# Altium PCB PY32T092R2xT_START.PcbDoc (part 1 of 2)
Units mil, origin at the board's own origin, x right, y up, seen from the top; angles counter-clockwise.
Board outline 1771.65 x 3866.06 mil, 2 copper layers (Top Layer, Bottom Layer), stack 21 mil thick; 144 components, 162 nets, 571 pads, 266 vias.
Unrouted connection lines stored in the file: 5.
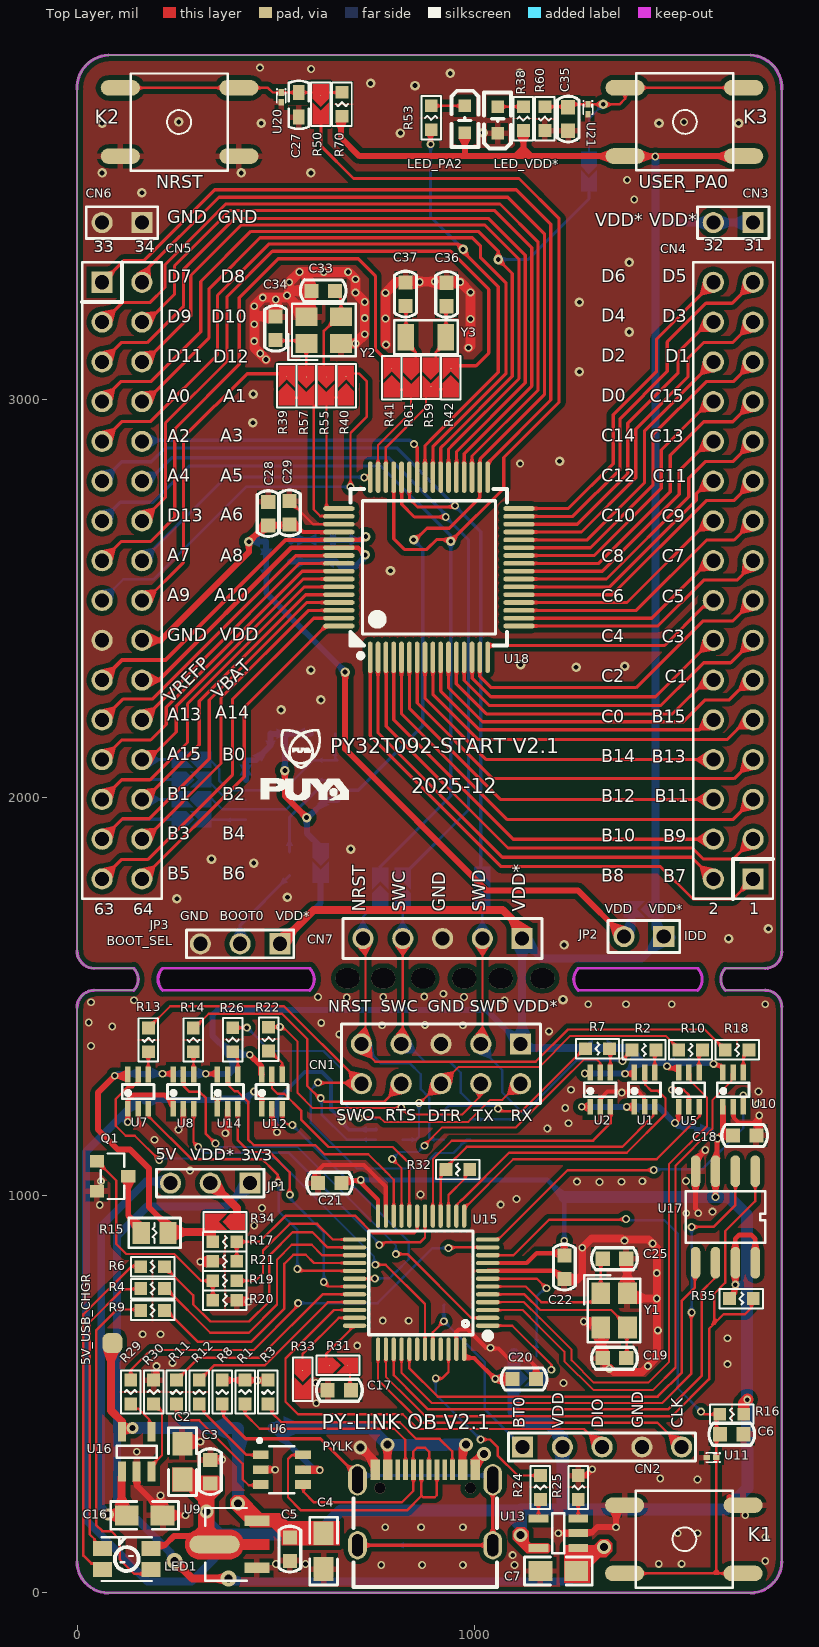
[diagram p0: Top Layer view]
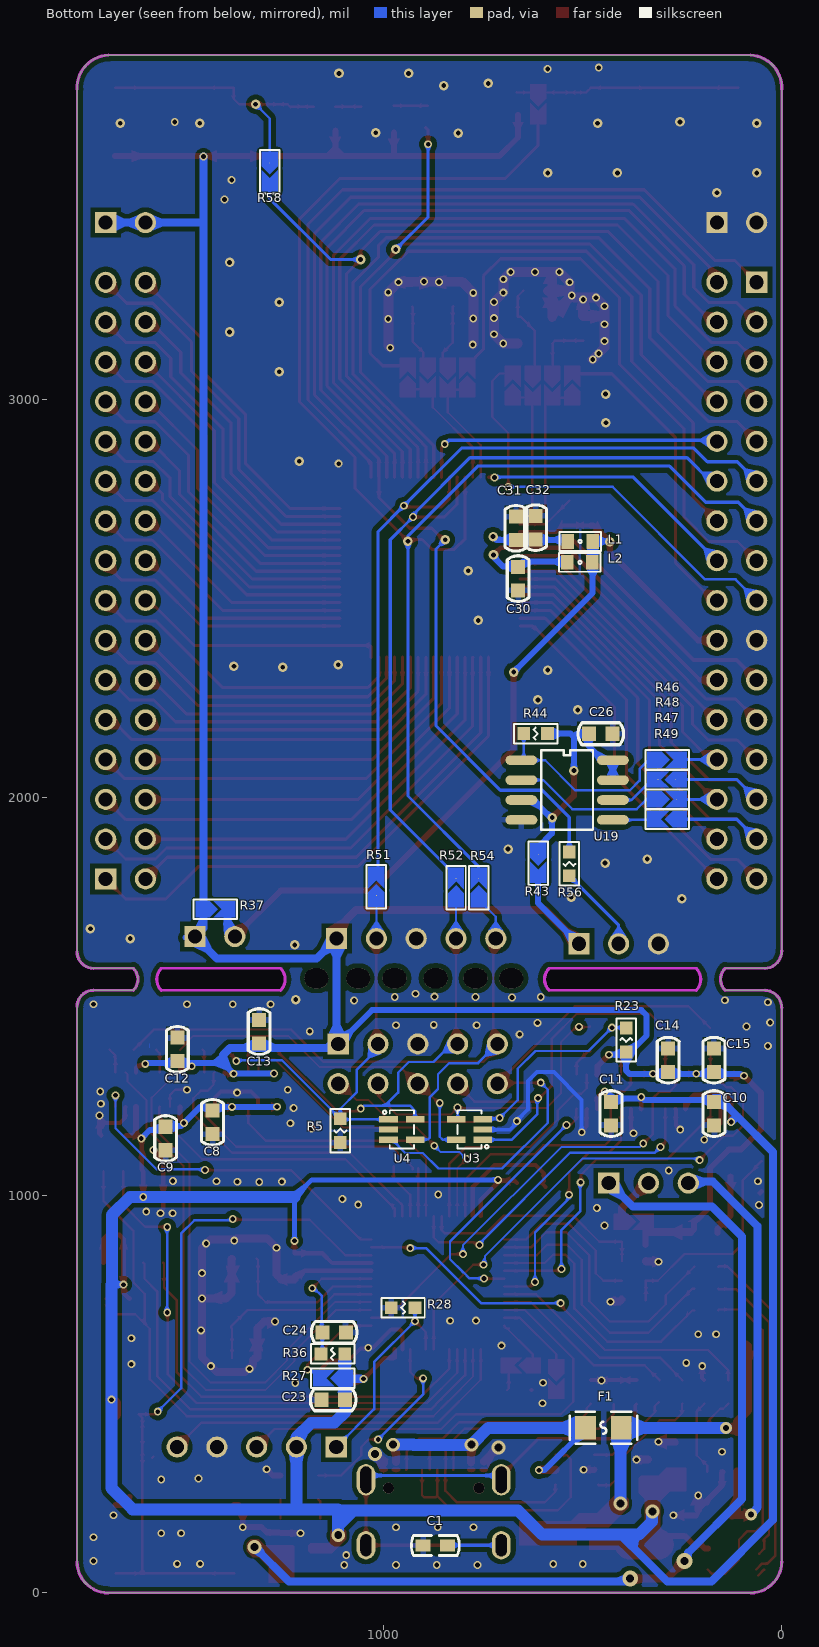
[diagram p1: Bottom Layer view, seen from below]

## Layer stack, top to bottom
Top Solder: solder mask 0.4, Solder Resist, Dk 3.5
Top Layer: signal copper 1.4
Dielectric 2: prepreg 2.8, Composite dielectric, Dk 4.1
Dielectric 1: prepreg 12.6, Composite dielectric, Dk 4.1
Dielectric 3: prepreg 2.8, Composite dielectric, Dk 4.1
Bottom Layer: signal copper 1.4
Bottom Solder: solder mask 0.4, Solder Resist, Dk 3.5

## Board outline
0.02,78.86 0.02,1470.12 cw(c43.77,1471.37) 42.52,1515.12 142.52,1515.12 ccw(c115.02,1542.62) 142.52,1570.12 42.52,1570.12 cw(c43.77,1613.87) 0.02,1615.12 0.02,3779.64 cw(c82.65,3783.54) 78.76,3866.18 1692.93,3866.18 cw(c1689.03,3783.54) 1771.67,3779.64 1771.67,1611.77 cw(c1730.02,1611.77) 1730.02,1570.12 1630.02,1570.12 ccw(c1657.52,1542.62) 1630.02,1515.12 1730.02,1515.12 cw(c1730.02,1473.46) 1771.67,1473.46 1771.67,78.86 cw(c1692.93,78.86) 1692.93,0.12 78.76,0.12 cw(c78.76,78.86)
cut-out: 215.02,1515.12 cw(c242.52,1542.62) 215.02,1570.12 585.02,1570.12 cw(c557.52,1542.62) 585.02,1515.12 565.02,1515.12
cut-out: 1260.02,1515.12 cw(c1287.52,1542.62) 1260.02,1570.12 1560.02,1570.12 cw(c1532.52,1542.62) 1560.02,1515.12

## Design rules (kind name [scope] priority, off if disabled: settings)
Clearance polygon [InPolygon] p1: gap=12 ignorepadtopadclearanceinfootprint=TRUE
Clearance [All] p2: gap=7 ignorepadtopadclearanceinfootprint=TRUE
HoleToHoleClearance [All] p1: gap=1 allowstackedmicrovias=TRUE
MinimumSolderMaskSliver [All] p1: minsoldermaskwidth=0
PlaneClearance [All] p1: clearance=8
PlaneConnect [All] p1: planeconnectstyle=Direct reliefexpansion=20 reliefentries=4 reliefconductorwidth=10 reliefairgap=10
PolygonConnect [All] p1: thpad.connectstyle=Direct thpad.reliefconductorwidth=10 thpad.reliefentries=4 thpad.polygonreliefangle="90 Angle" thpad.airgapwidth=10 smdpad.connectstyle=Relief smdpad.reliefconductorwidth=15 smdpad.reliefentries=4 smdpad.polygonreliefangle="90 Angle" smdpad.airgapwidth=10 via.connectstyle=Direct via.reliefconductorwidth=10 via.reliefentries=4 via.polygonreliefangle="90 Angle" via.airgapwidth=10
RoutingVias [All] p1: holewidth=28 width=50 viastyle="Through Hole" minholewidth=28 minwidth=50 maxholewidth=28 maxwidth=50
SilkToSilkClearance [All] p1: silktosilkclearance=0
SilkToSolderMaskClearance [IsPad] p1: minsilkscreentomaskgap=0 clearancetoexposedcopper=TRUE
SolderMaskExpansion [All] p1: expansion=4 istentingtop=FALSE
UnRoutedNet [All] p1: checkbadconnections=TRUE
Width [All] p1: maxlimit=100 minlimit=5 preferedwidth=8
23 further rules are at their usual default settings.

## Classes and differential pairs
component class PY32F092R2xT_START: 3 C26 C27 C28 C29 C30 C31 C32 C33 C34 C35 C36 C37 CN3 CN4 CN5 CN6 CN7 JP2 JP3 K2 K3 L1 L2 LED_PA2 LED_VDD* R37 R38 R39 R40 R41 R42 R43 R44 R46 R47 R48 R49 R50 R51 R52 R53 R54 R55 R56 R57 R58 R59 R60 R61 R70 U18 U19 U20 U21 Y2 Y3
component class PY32F403C1xT_LINK: 5V_USB_CHGR C1 C2 C3 C4 C5 C6 C7 C8 C9 C10 C11 C12 C13 C14 C15 C16 C17 C18 C19 C20 C21 C22 C23 C24 C25 CN1 CN2 F1 JP1 K1 LED1 PYLK Q1 R1 R2 R3 R4 R5 R6 R7 R8 R9 R10 R11 R12 R13 R14 R15 R16 R17 R18 R19 R20 R21 R22 R23 R24 R25 R26 R27 R28 R29 R30 R31 R32 R33 R34 R35 R36 U1 U2 U3 U4 U5 U6 U7 U8 U9 U10 U11 U12 U13 U14 U15 U16 U17 Y1

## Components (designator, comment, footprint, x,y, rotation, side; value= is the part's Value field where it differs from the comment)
5V_USB_CHGR "TP_SIN" TP_SIN 89.03,628.05 r90 top
C1 "4.7nF" C0603#1 870.87,119.29 r180 bottom
C2 "10uF" C0805 265.02,330.12 r270 top
C3 "100nF" C0603#2 335.02,305.12 r270 top
C4 "10uF" C0805 620.02,105.12 r90 top
C5 "100nF" C0603#2 535.02,110.12 r90 top
C6 "100nF" C0603#2 1646.06,398.88 r180 top
C7 "10uF" C0805 1210.02,55.12 r0 top
C8 "100nF" C0603#2 1431.02,1183.12 r90 bottom value=104
C9 "100nF" C0603#2 1548.92,1142.42 r90 bottom value=104
C10 "100nF" C0603#2 170.22,1205.02 r90 bottom value=104
C11 "100nF" C0603#2 429.02,1205.02 r90 bottom value=104
C12 "100nF" C0603#2 1519.42,1366.72 r270 bottom value=104
C13 "100nF" C0603#2 1313.82,1411.22 r270 bottom value=104
C14 "100nF" C0603#2 285.52,1339.32 r270 bottom value=104
C15 "100nF" C0603#2 170.52,1339.32 r270 bottom value=104
C16 "10uF" C0805 170.02,195.12 r180 top
C17 "100nF" C0603#2 659.61,509.61 r0 top
C18 "100nF" C0603#2 1678.35,1150 r180 top value=104
C19 "22pF" C0603#2 1351.14,590.12 r0 top
C20 "100nF" C0603#2 1123.88,537.71 r180 top value=104
C21 "100nF" C0603#2 635.02,1030.12 r0 top value=104
C22 "100nF" C0603#2 1225.14,819.12 r90 top value=104
C23 "100nF" C0603#2 1127.75,485.69 r180 bottom value=104
C24 "100nF" C0603#2 1125.14,655.12 r0 bottom value=104
C25 "22pF" C0603#2 1351.14,840.12 r180 top
C26 "100nF" C0603#2 454.91,2159.85 r0 bottom value=104
C27 "100nF" C0603#1 557.48,3740.94 r90 top
C28 "4.7uF" C0603#2 480.82,2713.43 r90 top
C29 "100nF" C0603#2 533.81,2715.26 r90 top
C30 "1uF" C0603#2 662.65,2549.82 r270 bottom
C31 "1uF" C0603#2 668.16,2676.43 r90 bottom
C32 "100nF" C0603#2 618.82,2677.94 r90 bottom
C33 "22pF" C0603#2 618.83,3273.44 r0 top
C34 "22pF" C0603#2 499.4,3179.12 r270 top
C35 "100nF" C0603#2 1234.75,3705.26 r90 top
C36 "22pF" C0603#2 929.21,3264.24 r270 top
C37 "22pF" C0603#2 826.04,3265.25 r270 top
CN1 "2X5P" HDR2X5 1115.02,1380.12 r180 top
CN2 "CON5" CON5 1120.06,366.88 r0 top
CN3 "CON2" CON2 1699.61,3444.88 r180 top
CN4 "2X16P 2.54mm" HDR-TH_32P-P2.54-V-M-R2-C16-S2.54-3 1649.61,2544.88 r90 top locked
CN5 "2X16P 2.54mm" HDR-TH_32P-P2.54-V-M-R2-C16-S2.54-3 113.06,2544.88 r270 top locked
CN6 "CON2" CON2 163.06,3444.88 r180 top
CN7 "Header 5" HDR1X5 1118.95,1645.12 r180 top
F1 "JK-SMD0805-050-16V" F0805 448.43,415.35 r180 bottom
JP1 "CON3" CON3 435.02,1030.12 r180 top
JP2 "CON2/NC" CON2 1475.02,1650.12 r180 top
JP3 "CON3" CON3 510.06,1631.88 r180 top
K1 "TS-KG02S-AT43F" SW-SMD_4P-L6.0-W6.0-P4.50-LS8.5 1527.56,134.82 r180 top
K2 "TS-KG02S-AT43F" SW-SMD_4P-L6.0-W6.0-P4.50-LS8.5 255.8,3697.92 r0 top
K3 "TS-KG02S-AT43F" SW-SMD_4P-L6.0-W6.0-P4.50-LS8.5 1528.95,3697.9 r180 top
L1 "BEAD" L0603 507,2643.32 r0 bottom value=600R@100MHz
L2 "BEAD" L0603 507.48,2590.94 r0 bottom value=600R@100MHz
LED1 "MHPA3528RGBCT" LED-ARRAY-SMD_4P-L3.5-W2.8-TL 125.02,85.12 r0 top
LED_PA2 "GREEN" 0603_LED 974.21,3690.35 r270 top
LED_VDD* "RED" 0603_LED 1058.21,3717.35 r90 top
PYLK "KH-TYPE-C-16P" USB-C-SMD_KH-TYPE-C-16P 875.22,214.93 r0 top locked
Q1 "2302" SOT23 89.39,1047.52 r90 top value=SI2302
R1 "5.1K" R0603 422.51,505.11 r270 top
R2 "27R" R0603 1425.22,1365.12 r180 top
R3 "5.1K" R0603 480.02,505.12 r90 top
R4 "680R" R0603 190.02,765.12 r0 top
R5 "1M" R0603 1109.84,1162.2 r90 bottom
R6 "680R" R0603 190.02,820.12 r0 top
R7 "27R" R0603 1308.41,1368.22 r180 top
R8 "1M" R0603 365.02,505.12 r90 top
R9 "680R" R0603 190.02,710.12 r0 top
R10 "27R" R0603 1542.37,1365.12 r180 top
R11 "27R" R0603 250.02,505.12 r90 top
R12 "27R" R0603 307.52,505.12 r90 top
R13 "27R" R0603 179.67,1390.2 r90 top
R14 "27R" R0603 292.32,1390.22 r90 top
R15 "100R" R0805 195.02,905.12 r0 top
R16 "10K" R0603 1646.06,448.88 r0 top
R17 "20K" R0603 371.53,882.72 r180 top
R18 "27R" R0603 1659.51,1365.12 r180 top
R19 "100R" R0603 371.54,784.9 r0 top
R20 "100K" R0603 371.53,736 r180 top
R21 "10K" R0603 371.54,833.8 r0 top
R22 "27R" R0603 481.65,1392.23 r90 top
R23 "4.7K" R0603 391.02,1390.12 r270 bottom
R24 "4.7K" R0603 1165.02,265.12 r270 top
R25 "16K" R0603 1260.24,264.96 r270 top
R26 "27R" R0603 391.22,1390.82 r90 top
R27 "0R" JP2_SMD 1128.36,539.95 r180 bottom
R28 "10K" R0603 952.02,717.19 r0 bottom
R29 "4.7K" R0603 135.02,505.12 r270 top
R30 "16K" R0603 192.52,505.12 r270 top
R31 "0R" JP2_SMD 656.23,571.86 r180 top
R32 "680R" R0603 957.48,1064.48 r0 top
R33 "0R" JP2_SMD 566.98,537.51 r90 top
R34 "0R" JP2_SMD 372.06,932.88 r0 top
R35 "100K" R0603 1670.02,740.12 r180 top
R36 "10K" R0603 1128.61,600.73 r180 bottom
R37 "0R" JP2_SMD 1423.77,1718.47 r0 bottom
R38 "680R" R0603 1122.21,3706.35 r270 top
R39 "0R" JP2_SMD 527.02,3035.12 r270 top
R40 "0R" JP2_SMD 676.23,3035.12 r270 top
R41 "0R" JP2_SMD 791.02,3055.12 r270 top
R42 "0R" JP2_SMD 940.02,3055.12 r270 top
R43 "0R/NC" JP2_SMD 612.32,1834.56 r90 bottom
R44 "100K" R0603 618.75,2160.34 r180 bottom
R46 "0R/NC" JP2_SMD 288.06,2094.88 r0 bottom
R47 "0R/NC" JP2_SMD 288.06,1994.88 r0 bottom
R48 "0R/NC" JP2_SMD 288.06,2044.88 r180 bottom
R49 "0R/NC" JP2_SMD 288.06,1944.88 r180 bottom
R50 "0R" JP2_SMD 612.6,3742.52 r90 top
R51 "100R" JP2_SMD 1018.95,1775.18 r270 bottom
R52 "100R" JP2_SMD 818.95,1773.12 r270 bottom
R53 "680R" R0603 890.21,3708.35 r270 top
R54 "0R" JP2_SMD 762.02,1773.12 r270 bottom
R55 "0R" JP2_SMD 626.5,3035.13 r90 top
R56 "10K" R0603 534.06,1832.88 r90 bottom
R57 "0R" JP2_SMD 576.76,3035.13 r90 top
R58 "0R" JP2_SMD 1287.02,3573.12 r90 bottom
R59 "0R" JP2_SMD 889.68,3055.94 r90 top
R60 "1.5K" R0603 1176.21,3706.35 r90 top
R61 "0R" JP2_SMD 840,3055.43 r90 top
R70 "10K" R0603 666.14,3742.52 r90 top
U1 "74LVC1T45DW" SOT363 1426.65,1265.12 r0 top
U2 "74LVC1T45DW" SOT363 1315.22,1265.12 r0 top
U3 "ESDALC6V1W5" ESD_SOT323-5L 785.02,1165.12 r90 bottom
U4 "ESDALC6V1W5" ESD_SOT323-5L 955.02,1165.12 r270 bottom
U5 "74LVC1T45DW" SOT363 1538.08,1265.12 r0 top locked
U6 "USBLC6-2SC6" SOT23-6 515.02,310.12 r90 top
U7 "74LVC1T45DW" SOT363 153.56,1260.12 r0 top locked
U8 "74LVC1T45DW" SOT363 267.28,1260.12 r0 top
U9 "LM1117F-3.3" SOT-89-3_L4.5-W2.5-P1.50-LS4.2-BR 399.06,122.05 r0 top
U10 "74LVC1T45DW" SOT363 1649.51,1265.12 r0 top
U11 "ESDALC6V1-1U2" ESD_ST0201 1595.02,340.12 r180 top
U12 "74LVC1T45DW" SOT363 490.14,1260.12 r0 top
U13 "MT9700" SOT23-5 1210.02,150.12 r90 top
U14 "74LVC1T45DW" SOT363 378.71,1260.12 r0 top
U15 "PY32F403C1xT" LQFP-48_L7.0-W7.0-P0.50-LS9.0-BL 865.02,780.12 r90 top locked
U16 "MT9700" SOT23-5 150.02,355.12 r0 top
U17 "P25Q64SH" SOP-8P 1630.02,945.12 r180 top value=SST25VF020B
U18 "PY32F092R2xT" LQFP-64_L10.0-W10.0-P0.50-LS12.0-BL 884.67,2578.43 r0 top locked
U19 "P25Q64SH" SOP-8P 539.58,2018.32 r270 bottom value=SST25VF020B
U20 "ESDALC6V1-1U2" ESD_ST0201 513.51,3759.59 r270 top
U21 "ESDALC6V1-1U2" ESD_ST0201 1284.25,3729.92 r270 top
Y1 "24MHz" CRYSTAL-SMD_4P-L3.2-W2.5-BL 1350.14,710.12 r270 top
Y2 "24MHz" CRYSTAL-SMD_4P-L3.2-W2.5-BL 620.36,3174.54 r0 top
Y3 "32.768KHz" CRYSTAL-SMD_L3.2-W1.5-1 877.12,3156.52 r0 top value=32.768kHz

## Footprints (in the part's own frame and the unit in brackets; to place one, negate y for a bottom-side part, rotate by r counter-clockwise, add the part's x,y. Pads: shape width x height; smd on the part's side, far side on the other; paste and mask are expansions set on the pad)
0603_LED [mil]
  rect 31.5x31.5 smd: 1(19,1) 2(-48,1)
  silkscreen extent -86,-33 55,35
C0603#1 [mil]
  rect 38x30 smd: 1(-31,0) 2(31,0)
  silkscreen extent -60,-25 60,25
C0603#2 [mil]
  rect 35.43x35.43 smd: 1(-29.53,0) 2(29.53,0)
  silkscreen extent -57,-28 57,28
C0805 [mil]
  rect 60x50 smd: 1(-45,0) 2(45,0)
  silkscreen extent -85,-35 85,35
CON2 [mm]
  rect 1.35x1.35 hole 0.9: 1(0,0)
  round 1.35 hole 0.9: 2(2.54,0)
  silkscreen extent -1.02,-1.02 3.56,1.02
CON3 [mm]
  rect 1.35x1.35 hole 0.9: 1(0,0)
  round 1.35 hole 0.9: 2(2.54,0) 3(5.08,0)
  silkscreen extent -0.89,-0.89 5.97,0.89
CON5 [mm]
  rect 1.35x1.35 hole 0.9: 1(0,0)
  round 1.35 hole 0.9: 2(2.54,0) 3(5.08,0) 4(7.62,0) 5(10.16,0)
  silkscreen extent -0.89,-0.89 11.05,0.89
CRYSTAL-SMD_4P-L3.2-W2.5-BL [mm]
  rect 1.4x1.2 smd: 1(-1.1,-0.85) 2(1.1,-0.85) 3(1.1,0.85) 4(-1.1,0.85)
  silkscreen extent -2.26,-1.91 2.03,1.68
CRYSTAL-SMD_L3.2-W1.5-1 [mm]
  rect 1.05x1.7 smd: 1(-1.275,0) 2(1.275,0)
  silkscreen extent -2.03,-1.08 2.03,1.08
ESD_SOT323-5L [mm]
  rect 0.4x1.2 smd mask+0.05: 1(-0.65,-0.85) 2(0,-0.85) 3(0.65,-0.85) 4(0.65,0.85) 5(-0.65,0.85)
  silkscreen extent -1.23,-1.21 1.23,0.77, body extent -1.15,-1.05 1.15,1.05, height 1.1
ESD_ST0201 [mm]
  rect 0.425x0.33 smd mask+0.05: 1(-0.312,0) 2(0.312,0)
  silkscreen extent -0.55,-0.3 0.33,0.3, body extent -0.34,-0.18 0.34,0.18, height 0.34
F0805 [mm]
  rect 1.335x1.5 smd paste-100 mask+0.051: 1(-1.142,0) 2(1.142,0)
  silkscreen extent -2.16,-1.02 2.16,1.02
HDR1X5 [mm] "Connector; Header; 5 Position"
  rect 1.35x1.35 hole 0.9: 1(0,0)
  round 1.35 hole 0.9: 2(2.54,0) 3(5.08,0) 4(7.62,0) 5(10.16,0)
  silkscreen extent -1.27,-1.27 11.43,1.27
HDR2X5 [mm] "Connector; Header; 4x2 Position"
  rect 1.35x1.35 hole 0.9: 1(0,0)
  round 1.35 hole 0.9: 2(0,2.54) 3(2.54,0) 4(2.54,2.54) 5(5.08,0) 6(5.08,2.54) 7(7.62,0) 8(7.62,2.54) 9(10.16,0) 10(10.16,2.54)
  silkscreen extent -1.27,-1.27 11.43,3.81
HDR-TH_32P-P2.54-V-M-R2-C16-S2.54-3 [mm]
  rect 1.35x1.35 hole 0.9: 1(-19.05,-1.27)
  round 1.35 hole 0.9: 2(-19.05,1.27) 3(-16.51,-1.27) 4(-16.51,1.27) 5(-13.97,-1.27) 6(-13.97,1.27) 7(-11.43,-1.27) 8(-11.43,1.27) 9(-8.89,-1.27) 10(-8.89,1.27) 11(-6.35,-1.27) 12(-6.35,1.27) 13(-3.81,-1.27) 14(-3.81,1.27) 15(-1.27,-1.27) 16(-1.27,1.27) 17(1.27,-1.27) 18(1.27,1.27) 19(3.81,-1.27) 20(3.81,1.27) 21(6.35,-1.27) 22(6.35,1.27) 23(8.89,-1.27) 24(8.89,1.27) 25(11.43,-1.27) 26(11.43,1.27) 27(13.97,-1.27) 28(13.97,1.27) 29(16.51,-1.27) 30(16.51,1.27) 31(19.05,-1.27) 32(19.05,1.27)
  silkscreen extent -20.32,-2.54 20.32,2.54
JP2_SMD [mil]
  round 1 smd: 1(21.75,0) 2(-23.03,0.03)
  Top Layer region: -49.77,20.03 -49.77,20.03 3.72,20.03 -16.28,0.03 3.72,-19.98 -49.78,-19.98 -49.78,-19.98
  Top Layer region: -6.25,0 13.75,20 49.75,20 49.75,-20 49.75,-20 13.75,-20
  silkscreen extent -55,-25 54,25
L0603 [mm]
  rect 0.8x0.95 smd mask+0.05: 1(-0.8,0) 2(0.8,0)
  silkscreen extent -1.33,-0.6 1.33,0.6, body extent -0.87,-0.47 0.87,0.47, height 0.95
LED-ARRAY-SMD_4P-L3.5-W2.8-TL [mm]
  rect 1.2x0.95 smd: 1(1.55,0.665) 2(1.55,-0.665) 3(-1.55,-0.665) 4(-1.55,0.665)
  silkscreen extent -1.6,-1.4 1.6,1.4
LQFP-48_L7.0-W7.0-P0.50-LS9.0-BL [mm]
  oval 0.27x1.5 smd mask+0.05: 1(-2.75,-4.25) 2(-2.25,-4.25) 3(-1.75,-4.25) 4(-1.25,-4.25) 5(-0.75,-4.25) 6(-0.25,-4.25) 7(0.25,-4.25) 8(0.75,-4.25) 9(1.25,-4.25) 10(1.75,-4.25) 11(2.25,-4.25) 12(2.75,-4.25) 25(2.75,4.25) 26(2.25,4.25) 27(1.75,4.25) 28(1.25,4.25) 29(0.75,4.25) 30(0.25,4.25) 31(-0.25,4.25) 32(-0.75,4.25) 33(-1.25,4.25) 34(-1.75,4.25) 35(-2.25,4.25) 36(-2.75,4.25)
  oval 1.5x0.27 smd mask+0.05: 13(4.25,-2.75) 14(4.25,-2.25) 15(4.25,-1.75) 16(4.25,-1.25) 17(4.25,-0.75) 18(4.25,-0.25) 19(4.25,0.25) 20(4.25,0.75) 21(4.25,1.25) 22(4.25,1.75) 23(4.25,2.25) 24(4.25,2.75) 37(-4.25,2.75) 38(-4.25,2.25) 39(-4.25,1.75) 40(-4.25,1.25) 41(-4.25,0.75) 42(-4.25,0.25) 43(-4.25,-0.25) 44(-4.25,-0.75) 45(-4.25,-1.25) 46(-4.25,-1.75) 47(-4.25,-2.25) 48(-4.25,-2.75)
  silkscreen extent -3.59,-4.46 3.3,3.34
LQFP-64_L10.0-W10.0-P0.50-LS12.0-BL [mm]
  oval 0.3x2 smd: 1(-3.75,-5.75) 2(-3.25,-5.75) 3(-2.75,-5.75) 4(-2.25,-5.75) 5(-1.75,-5.75) 6(-1.25,-5.75) 7(-0.75,-5.75) 8(-0.25,-5.75) 9(0.25,-5.75) 10(0.75,-5.75) 11(1.25,-5.75) 12(1.75,-5.75) 13(2.25,-5.75) 14(2.75,-5.75) 15(3.25,-5.75) 16(3.75,-5.75) 33(3.75,5.75) 34(3.25,5.75) 35(2.75,5.75) 36(2.25,5.75) 37(1.75,5.75) 38(1.25,5.75) 39(0.75,5.75) 40(0.25,5.75) 41(-0.25,5.75) 42(-0.75,5.75) 43(-1.25,5.75) 44(-1.75,5.75) 45(-2.25,5.75) 46(-2.75,5.75) 47(-3.25,5.75) 48(-3.75,5.75)
  oval 2x0.3 smd: 17(5.75,-3.75) 18(5.75,-3.25) 19(5.75,-2.75) 20(5.75,-2.25) 21(5.75,-1.75) 22(5.75,-1.25) 23(5.75,-0.75) 24(5.75,-0.25) 25(5.75,0.25) 26(5.75,0.75) 27(5.75,1.25) 28(5.75,1.75) 29(5.75,2.25) 30(5.75,2.75) 31(5.75,3.25) 32(5.75,3.75) 49(-5.75,3.75) 50(-5.75,3.25) 51(-5.75,2.75) 52(-5.75,2.25) 53(-5.75,1.75) 54(-5.75,1.25) 55(-5.75,0.75) 56(-5.75,0.25) 57(-5.75,-0.25) 58(-5.75,-0.75) 59(-5.75,-1.25) 60(-5.75,-1.75) 61(-5.75,-2.25) 62(-5.75,-2.75) 63(-5.75,-3.25) 64(-5.75,-3.75)
  silkscreen extent -5,-5.79 5,5
R0603 [mil]
  rect 32x32 smd: 1(-30,0) 2(30,0)
  silkscreen extent -55,-25 55,25
R0805 [mm]
  rect 1.1x1.4 smd: 1(-0.85,0) 2(0.85,0)
  silkscreen extent -1.65,-0.95 1.65,0.95
SOP-8P [mil]
  oval 24x80 smd: 1(-75,-115) 2(-25,-115) 3(25,-115) 4(75,-115) 5(75,115) 6(25,115) 7(-25,115) 8(-75,115)
  silkscreen extent -100,-65 100,65
SOT23 [mm]
  rect 0.8x0.9 smd: 1(0.95,1) 2(-0.95,1) 3(0,-1)
  silkscreen extent -1.45,-0.75 1.45,0.75
SOT23-5 [mil]
  rect 20x50 smd: 1(-37.5,-50) 2(0,-50) 3(37.5,-50) 4(37.5,50) 5(-37.5,50)
  silkscreen extent -50,-15 50,15
SOT23-6 [mm]
  rect 0.55x1 smd: 1(0.95,1.35) 2(0,1.35) 3(-0.95,1.35) 4(-0.95,-1.35) 5(0,-1.35) 6(0.95,-1.35)
  silkscreen extent -1.5,-0.8 1.96,1.52
SOT363 [mm]
  rect 0.35x1 smd: 1(-0.65,-1.1) 2(0,-1.1) 3(0.65,-1.1) 4(0.65,1.1) 5(0,1.1) 6(-0.65,1.1)
  silkscreen extent -1.02,-0.45 1.02,0.45, body extent -1,-1.1 1,1.16, height 1
SOT-89-3_L4.5-W2.5-P1.50-LS4.2-BR [mm]
  rect 1.575x0.672 smd: 1(1.356,-1.5) 3(1.356,1.5)
  oval 3.226x1.14 smd: 2(-1.356,0)
  Top Layer region: -2.283,0.95 -0.429,0.95 -0.384,0.949 -0.34,0.946 -0.296,0.94 -0.252,0.933 -0.208,0.924 -0.165,0.912 -0.123,0.899 -0.081,0.884 -0.04,0.866 0,0.847 0.04,0.826 0.078,0.803 0.115,0.779 0.151,0.752 0.185,0.724 0.219,0.695 0.251,0.664 0.281,0.631 0.31,0.597 0.337,0.562 0.362,0.525 0.386,0.488 0.408,0.449 0.428,0.409 0.447,0.33 2.144,0.33 2.144,-0.33 0.447,-0.33 0.428,-0.409 0.408,-0.449 0.386,-0.488 0.362,-0.526 0.337,-0.562 0.31,-0.597 0.281,-0.631 0.251,-0.664 0.219,-0.695 0.185,-0.725 0.151,-0.753 0.115,-0.779 0.078,-0.804 0.04,-0.827 0,-0.848 -0.04,-0.867 -0.081,-0.884 -0.123,-0.899 -0.165,-0.913 -0.208,-0.924 -0.252,-0.934 -0.296,-0.941 -0.34,-0.946 -0.384,-0.949 -0.429,-0.95 -2.283,-0.95 -2.328,-0.949 -2.372,-0.946 -2.416,-0.941 -2.46,-0.934 -2.504,-0.924 -2.547,-0.913 -2.589,-0.899 -2.631,-0.884 -2.672,-0.867 -2.713,-0.848 -2.752,-0.827 -2.79,-0.804 -2.827,-0.779 -2.863,-0.753 -2.898,-0.725 -2.931,-0.695 -2.963,-0.664 -2.993,-0.631 -3.022,-0.597 -3.049,-0.562 -3.075,-0.526 -3.098,-0.488 -3.12,-0.449 -3.141,-0.409 -3.159,-0.369 -3.175,-0.327 -3.189,-0.285 -3.202,-0.242 -3.212,-0.199 -3.22,-0.155 -3.227,-0.111 -3.231,-0.067 -3.233,-0.022 -3.233,0.022 -3.231,0.067 -3.227,0.111 -3.22,0.155 -3.212,0.199 -3.202,0.242 -3.189,0.285 -3.175,0.327 -3.159,0.369 -3.141,0.409 -3.12,0.449 -3.098,0.488 -3.075,0.525 -3.049,0.562 -3.022,0.597 -2.993,0.631 -2.963,0.664 -2.931,0.695 -2.898,0.724 -2.863,0.752 -2.827,0.779 -2.79,0.803 -2.752,0.826 -2.713,0.847 -2.672,0.866 -2.631,0.884 -2.589,0.899 -2.547,0.912 -2.504,0.924 -2.46,0.933 -2.416,0.94 -2.372,0.946 -2.328,0.949 -2.283,0.95
  silkscreen extent -1.95,-2.33 0.7,2.33
SW-SMD_4P-L6.0-W6.0-P4.50-LS8.5 [mm]
  oval 2.5x1 smd: 1(-3.734,2.177) 2(3.835,2.177) 3(-3.734,-2.184) 4(3.835,-2.184)
  silkscreen extent -3.08,-3.1 3.12,3.09, body extent -4.48,-3 4.52,3, height 8.95
TP_SIN [mil]
  rrect60% 50x50 smd: 1(0,0)
USB-C-SMD_KH-TYPE-C-16P [mm]
  oval 1.2x2 hole 0.7 slot 1.7 at 90 deg: 1(-4.32,1.765) 2(4.32,1.765)
  oval 1.2x1.8 hole 0.7 slot 1.4 at 90 deg: 3(-4.32,-2.415) 4(4.32,-2.415)
  rect 0.3x1.3 smd: A1(-3.35,2.415) A4(-2.55,2.415) A5(-1.25,2.415) A6(-0.25,2.415) A7(0.25,2.415) A8(1.25,2.415) A9(2.55,2.415) A12(3.35,2.415) B1(3.05,2.415) B4(2.25,2.415) B5(1.75,2.415) B6(0.75,2.415) B7(-0.75,2.415) B8(-1.75,2.415) B9(-2.25,2.415) B12(-3.05,2.415)
  round 0.7 hole 0.7 unplated: ""(-2.89,1.235) ""(2.89,1.235)
  silkscreen extent -4.57,-5.08 4.57,0.57

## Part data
C1 C3 C5 C6 C17 C19 C25 C27 C28 C29 C30 C31 C32 C33 C34 C35 C36 C37: library part C0603
C2 C4 C7 C16: library part C0805
C8 C9 C10 C11 C12 C13 C14 C15 C18 C20 C21 C22 C23 C24 C26: library part 贴片高压陶瓷电容, "Capacitor (Semiconductor SIM Model)"
CN1: Color=黑色, Current Rating (Max)=-, JLCPCB Part Class="Extended Part", LCSC Part Name="间距:2.54mm 2x5P 直插 方针", Manufacturer=XFCN(兴飞), Manufacturer Part=PZ254V-12-10P, Operating Temperature Range=-40℃~+105℃
CN4 CN5: Color=黑色, Current Rating (Max)=3A, JLCPCB Part Class="Extended Part", LCSC Part Name="2x16P 间距:2.54mm 方针", Manufacturer="XKB Connection(中国星坤)", Manufacturer Part=X6522WV-2x16H-C60D30-E80, Operating Temperature Range=-40℃~+105℃, Soldering Temperature(Max)=260℃, Voltage Rating (Max)=250V
CN7: "Header, 5-Pin"
F1: Current - Max=100A, Hold Current=500mA, JLCPCB Part Class="Extended Part", LCSC Part Name="6V 0.5A 贴片自恢复", Manufacturer=JK(金科), Operating Temperature=-40℃~+85℃, Power Dissipation=600mW, Resistance - Initial (Ri) (Min)=150mΩ, Resistance - Post Trip (R1) (Max)=850mΩ, Trip Current=1A, Voltage - Max=6V
JP2: library part CON2_DIP
K1 K2 K3: Actuator/Cap Color=黑色, Contact Current=50mA, Insulation Resistance=100MΩ, JLCPCB Part Class=扩展库, LCSC Part Name="6*6*4.3mm 立贴 轻触开关", Manufacturer=HANBO(汉博), Operating Force=250gf, Voltage Rating (DC)=12V
L1 L2: "SMD Chip ferrite bead, 600R@100MHz +/-25%, 350mA, 500mohm DC, 0603, T=0.8mm", Manufacturer=TAI-TECH, Manufacturer_Part_Number=FCM1608KF-601T03
LED1: JLCPCB Part Class=扩展库, LCSC Part Name=RGB三色, Manufacturer=MEIHUA(美华)
LED_PA2 LED_VDD*: library part PDI-E803_Dup1
PYLK: BOM_JLCPCB Part Class="Extended Part", BOM_Manufacturer="Shenzhen Kinghelm Elec"
Q1: library part "MOSFET N", "MOSFET N"
R1 R2 R3 R4 R5 R6 R7 R8 R9 R10 R11 R12 R13 R14 R16 R17 R18 R19 R20 R21 R22 R23 R24 R26 R27 R28 R29 R31 R32 R33 R34 R35 R36 R37 R38 R39 R40 R41 R42 R43 R44 R46 R47 R48 R49 R50 R51 R52 R53 R54 R55 R56 R57 R58 R59 R60 R61 R70: library part R0603
R15: library part R0805
R25 R30: library part R0603_7, "0603WAF1602T5E 16KΩ(1602) ±1%"
U3 U4: "Dual Transil array for ESD protection", Manufacturer=STMICROELECTRONICS
U11 U20 U21: "ESD protection 6V1", Manufacturer=STMICROELECTRONICS
U15: "LQFP48", BOM_Manufacturer=PUYA(普冉)
U17 U19: library part SST25VF010, "SST25VF010"
U18: library part PY32L090R2xTx, "LQFP64", BOM_Manufacturer=PUYA(普冉), BOM_Manufacturer Part=PY32CA00R1x
Y1 Y2: library part ABM8AIG-24.000MHZ-82Z-T, "±20ppm , 12.5pF , T_use: -40°C~125°C", Equivalent Series Resistance (ESR)=50Ω, External load capacitor=8pF, Frequency Stability(Full temperature range)=±50ppm, JLCPCB Part Class="Extended Part", LCSC Part Name="24MHz ±20ppm 8pF", Manufacturer=ABRACON, Normal temperature Frequency Tolerance=±20ppm, Operating Temperature=-40℃~+125℃
Y3: library part XKXGI-SUA-32.768K, "±20ppm , 12.5pF , T_use: -40°C~125°C", External load capacitor=12.5pF, Frequency Stability(Full temperature range)=±30ppm, JLCPCB Part Class="Extended Part", LCSC Part Name="32.768kHz ±20ppm 12.5pF YST310S", Manufacturer=YXC(扬兴晶振), Normal temperature Frequency Tolerance=±20ppm, Operating Temperature=-40℃~+85℃

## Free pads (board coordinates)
  oval 60x50 hole 50 slot 60 at 0 deg unplated: 1(680.02,1545.12) 1(770.02,1545.12) 1(870.08,1545.28) 1(973.56,1545.12) 1(1065.02,1545.12) 1(1170.02,1545.12)

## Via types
v1: diameter 19.68, hole 11.81, Top Layer to Bottom Layer, tented both sides, 132 vias
v2: diameter 19.68, hole 11.81, Top Layer to Bottom Layer, 72 vias
v3: diameter 24, hole 12, Top Layer to Bottom Layer, tented both sides, 50 vias
v4: diameter 35, hole 20, Top Layer to Bottom Layer, tented both sides, 8 vias
v5: diameter 30, hole 15, Top Layer to Bottom Layer, tented both sides, 2 vias
v6: diameter 40, hole 20, Top Layer to Bottom Layer, tented both sides, 2 vias

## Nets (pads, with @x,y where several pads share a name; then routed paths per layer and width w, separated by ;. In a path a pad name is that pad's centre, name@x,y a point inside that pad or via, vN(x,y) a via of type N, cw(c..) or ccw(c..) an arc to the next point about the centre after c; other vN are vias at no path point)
3.3V_OUT_EN: R24.1 U15.46 | length 497.1
  Top Layer w6: v1(901.61,539.48) 917.66,539.48 933.92,555.74 U15.46@933.92,612.8 ; v1(1014.7,385.65) 1038.6,385.65 1057.36,366.89 1057.36,345.58 1107.83,295.12 R24.1@1165.02,295.12
  Bottom Layer w6: v1(901.61,539.48) 901.61,498.74 v1(1014.7,385.65)
3V3_PYLK: C2.2 C3.2 C8.2 C9.2 C10.2 C11.2 C18.2 C20.2 C21.2 C22.2 C23.2 CN2.2 LED1.1 R16.2 R27.1 R35.2 R36.2 U1.1 U2.1 U5.1 U7.1 U8.1 U9.2 U10.1 U12.1 U13.5 U14.1 U15.9 U15.24 U15.48 U17.3 U17.7 U17.8 | length 7826.5
  Top Layer w10: v1(445.18,1260.74) 449.44,1260.74 464.55,1245.64 U12.1@464.55,1216.81 ; C21.2@666.02,1030.12 C21.2@670.67,1034.77 ; C22.2@1225.02,854.24 v1(1225.02,885.12)
  Top Layer w11: v1@710.02,1035.12 756.75,988.39 U15.24@756.75,947.44 ; U15.48@973.29,612.8 973.29,590.72 973.47,590.54 998.24,590.54 1053.66,535.12 v1@1055.14,535.12 ; U15.9@1032.34,829.33 1130.4,829.33 1155.32,854.24 C22.2@1225.02,854.24
  Top Layer w12: v2(127.37,1183.78) 127.97,1184.38 U7.1@127.97,1216.81 127.97,1237.99 141.98,1251.99 219.82,1251.99 241.69,1230.13 U8.1@241.69,1216.81 ; U14.1@353.12,1216.81 354.01,1217.7 353.13,1218.57 v1(353.13,1246.51) ; C21.2@670.67,1034.77 672,1036.1 711,1036.1 v1(713.3,1038.4) ; v1(1268.74,1222.14) 1269.08,1221.81 U2.1@1289.63,1221.81 ; v1(1382.02,1222.02) 1382.22,1221.81 U1.1@1401.06,1221.81 ; v2(1503.03,1181.14) 1512.49,1190.6 U5.1@1512.49,1221.81 1511.6,1220.92 U5.1@1511.82,1220.7 ; v1(1605.02,995.12) U17.3@1605.02,1060.11 1609.03,1064.12 1609.03,1141.37 v1(1609.89,1142.23) ; 1617.77,1150.12 C18.2@1649.02,1150.12 ; R35.2@1640.02,740.12 1655.02,755.12 v1(1655.02,775.12) U17.7@1655.02,830.11 1655.02,890.12 1665.02,900.12 1695.02,900.12 1705.02,890.12 U17.8@1705.02,830.11
  Top Layer w15: LED1.1@186.04,111.3 193.5,111.3 193.5,111.77 202.16,120.43 221.05,120.43 244.32,143.7 U9.2@313.81,143.7 ; v1(1609.89,1142.23) 1617.77,1150.12 1623.92,1156.26 U10.1@1623.92,1221.81
  Top Layer w20: v1@1054.88,537.71 C20.2@1092.88,537.71
  Top Layer w30: R16.2@1676.06,448.88 1676.06,476.88 v1(1685.06,485.88)
  Bottom Layer w6: 1093.36,544.95 1096.75,541.55 1098.36,539.95
  Bottom Layer w12: v1(713.3,1038.4) 1181.73,1038.4 1225.02,995.12 ; v1(1225.02,885.12) 1225.02,990.12 ; v1(1655.02,775.12) 1683.75,775.12 1684.67,775.12
  Bottom Layer w15: C10.2@170.22,1236.02 173.66,1239.46 346.08,1239.46 v1(353.13,1246.51) 356.93,1242.71 422.32,1242.71 429.02,1236.02 429.02,1244.58 v1(445.18,1260.74) v1@443.58,1262.34 ; v1(1268.74,1222.14) 1462.02,1222.14 v2(1503.03,1181.14) 1510.75,1173.42 C9.2@1548.92,1173.42 ; C9.2@1558.33,1164 1588.12,1164 v1(1609.89,1142.23)
  Bottom Layer w20: v2(127.37,1183.78) 112.88,1198.27 111.67,1198.27 ; C10.2@170.22,1244.32 157.72,1244.32 111.67,1198.27 ; 405.31,146.37 287.9,28.96 176.95,28.96 22.02,183.89 22.02,1108.62 111.67,1198.27 ; v1(1051.41,538.12) 1096.75,538.12
  Bottom Layer w30: v4(325.02,205.12) 325.97,204.16 325.97,180.03 359.63,146.37 405.31,146.37 602.15,146.37 663.21,207.43 1115.97,207.43 ; 1096.75,541.55 1096.75,538.12 1096.75,485.69 1096.75,455.92 1124.79,427.88 1183.06,427.88 1220.06,390.88 CN2.2@1220.06,366.88 1220.06,211.12 1221.06,210.12 ; R36.2@1098.61,600.73 1098.61,547.94 R27.1@1106.61,539.94 ; v4(1115.02,145.12) 1115.97,146.07 1115.97,207.43 ; 1225.02,995.12 v1(1605.02,995.12) 1638.98,995.12 1683.75,950.34 1683.75,775.12 ; 1684.67,363.3 1684.67,775.12 ; 1685.06,360.71 1685.06,263.3 1631.87,210.12 1221.06,210.12 ; 1115.97,207.43 1115.97,210.12 1221.06,210.12
3V3_USB_PYLK: C7.2 JP1.1 U13.1 | length 2404.2
  Top Layer w20: v6@245.81,80.12 290.04,35.89 v6(380.98,35.89)
  Bottom Layer w20: v6(245.02,80.12) 245.02,85.53 235.29,95.25 235.29,101.1 100.11,236.27 100.11,895.98 175.61,971.48 374.62,971.48 418.26,1015.12 420.02,1015.12 433.26,1028.36 JP1.1@433.26,1030.12 ; v6(380.98,35.89) 387.84,29.03 1238.93,29.03 v4(1325.02,115.12) v4@1326.8,113.34
5V_OUT_EN: R29.1 U15.11 | length 1053.8
  Top Layer w6: R29.1@135.02,535.12 135.02,560.12 185.67,610.77 444.43,610.77 555.94,722.27 v1(555.94,728.54) ; v1(934.06,866.88) 935.87,868.7 U15.11@1032.34,868.7
  Bottom Layer w6: v1(555.94,728.54) 755.71,728.54 894.06,866.88 v1(934.06,866.88)
5V_USB_CHGR: 5V_USB_CHGR.1 C4.2 C5.2 F1.2 U9.3 U16.5 | length 712.3
  Top Layer w20: 5V_USB_CHGR.1@90.02,625.12 85.23,620.33 85.23,458.61 112.52,431.33 U16.5@112.52,405.12 ; U16.5@112.52,413.2 138.1,413.2 v5(140.02,415.12)
  Bottom Layer w30: v5(140.02,415.12) F1.2@402.11,415.12 ; v4(405.02,225.12) F1.2@405.02,413.78
5V_USB_PYLK: C16.2 JP1.3 U16.1 | length 1109.9
  Top Layer w20: v5(77.41,196.94) 78.32,196.03 124.1,196.03 C16.2@125.02,195.12 ; U16.1@112.52,304.8 112.52,290.12 112.2,289.8 112.2,210.12 C16.2@125.02,210.12
  Bottom Layer w20: v5(77.41,196.94) 74.93,197.43 71.22,201.15 69.82,202.55 60.94,215.88 60.94,922 172.86,1033.93 231.2,1033.93 JP1.3@235.02,1030.12
AD_TVDD: R17.1 R21.2 U15.19 | length 586.3
  Top Layer w6: R21.2@401.53,833.81 R17.1@401.53,882.72 458.8,882.72 523.98,947.9 699.68,947.9 743.6,903.98 846.87,903.98 855.18,912.28 U15.19@855.18,947.44
BOOT0: CN5.2 R56.2 U18.34 | length 3085.6
  Top Layer w8: CN5.2@163.06,3294.88 163.06,3314.73 356.95,3508.62 1083.32,3508.62 1175.02,3416.93 1175.02,3012.55 1013.35,2850.88 1013.35,2805.53 U18.34@1012.62,2804.8 1012.62,2753.44 935.64,2676.47 879.74,2676.47 850.7,2647.43 v3(846.15,2647.43)
  Bottom Layer w8: R56.2@534.06,1862.88 534.06,1949.56 602.35,2017.86 707.29,2017.86 869.15,2179.72 869.15,2624.42 v3(846.15,2647.43)
DIR_RESET: U10.5 U15.3 | length 1394.4
  Top Layer w5: U15.3@1032.34,711.22 1120.68,711.22 1160.05,671.85 1225.23,606.66 1225.23,582.89 1297.79,510.33 1448.14,510.33 1504.55,566.74 1504.55,1074.16 1596.98,1166.59 1596.98,1238.57 1645.12,1286.7 1645.12,1304.03 U10.5@1649.51,1308.42
DIR_RTCK_DTR: U5.5 U15.4 | length 1362.6
  Top Layer w5: U15.4@1032.34,730.91 1123.7,730.91 1163.07,691.54 1243.45,611.16 1243.45,584.61 1299.11,528.95 1435.97,528.95 1488.55,581.53 1488.55,1078.44 1583.98,1173.87 1583.98,1245.2 1542.47,1286.71 1542.47,1304.03 U5.5@1538.08,1308.42
DIR_TCK_SWCLK: U2.5 U15.21 | length 808
  Top Layer w5: v1(792.14,1090.78) 815.81,1067.11 U15.21@815.81,947.44 ; v2(873.5,1124.24) 873.5,1125.68 917.35,1169.53 1102.35,1169.53 1216.73,1283.9 1273.4,1340.57 1307.2,1340.57 1315.22,1332.55 U2.5@1315.22,1308.42
  Bottom Layer w5: v1(792.14,1090.78) 809.63,1108.27 857.53,1108.27 v2(873.5,1124.24)
DIR_TDI_VCP_TX: U12.5 U15.20 | length 603.7
  Top Layer w6: U12.5@490.14,1303.42 490.14,1268.89 503.93,1255.09 520.99,1255.09 563.27,1212.81 563.27,1190.03 632.12,1121.18 793.66,1121.18 835.49,1079.35 U15.20@835.49,947.44
DIR_TDO_SWO: U7.5 U15.43 | length 1250.3
  Top Layer w6: U7.5@153.56,1303.42 153.56,1284.85 140.21,1271.49 127.24,1271.49 97.42,1241.67 97.42,1174.39 122.49,1149.32 145.27,1149.32 v2(206.56,1088.02) ; v1(750.02,825.12) 775.7,825.12 874.86,725.96 U15.43@874.86,612.8
  Bottom Layer w5: v2(206.56,1088.02) 211.07,1092.52 500.23,1092.52 746.38,846.37 746.38,828.75 v1(750.02,825.12)
DIR_TMS_SWDIO: U1.5 U15.14 | length 784.3
  Top Layer w6: U15.14@953.6,947.44 953.6,974.1 956.97,977.48 956.97,978.41 966.53,987.96 967.45,987.96 1086.14,1106.65 1381.82,1106.65 1479.41,1204.25 1479.41,1243.48 1460.8,1262.09 1443.81,1262.09 1428.54,1277.36 1428.54,1306.54 U1.5@1426.65,1308.42
DIR_TRST_RTS: U8.5 U15.2 | length 1100.7
  Top Layer w6: U8.5@267.28,1303.42 267.87,1302.84 267.87,1274.36 282.55,1259.68 308.16,1259.68 323.96,1243.87 323.96,1153.91 v1(348.08,1129.79) ; v1(801.53,851.8) 830.73,851.8 991,691.54 U15.2@1032.34,691.54
  Bottom Layer w5: v1(348.08,1129.79) 356.34,1121.52 553.6,1121.52 801.53,873.59 v1(801.53,851.8)
DIR_VCP_RX: U14.5 U15.22 | length 688.5
  Top Layer w6: U14.5@378.71,1303.42 380.09,1302.05 380.09,1277.25 396.62,1260.72 404.22,1260.72 430.02,1234.92 430.02,1140.17 444.62,1125.57 599.32,1125.57 622.06,1102.82 732.2,1102.82 776.39,1058.62 796.12,1038.9 U15.22@796.12,947.44
F_VDD: C26.2 R43.1 R44.2 U19.3 U19.7 U19.8 | length 687.5
  Top Layer w15: v3(522.62,2067.37) 522.62,2003.74 v3(577.15,1949.21)
  Bottom Layer w15: U19.7@424.57,2043.32 U19.8@424.58,2093.32 449.31,2093.32 485.91,2129.92 ; 486.4,2129.92 486.4,2160.34 485.91,2159.85 515.05,2159.85 522.62,2152.28 ; v3(522.62,2067.37) 522.62,2152.28 ; R44.2@588.75,2160.34 530.67,2160.34 522.62,2152.28 ; 612.32,1864.56 612.32,1875.24 577.95,1909.61 577.95,1948.4 v3(577.15,1949.21) 580.42,1949.21 624.53,1993.32 U19.3@654.57,1993.32
GND: C1.1 C2.1 C3.1 C4.1 C5.1 C6.1 C7.1 C8.1 C9.1 C10.1 C11.1 C12.1 C13.1 C14.1 C15.1 C16.1 C17.1 C18.1 C19.1 C20.1 C21.1 C22.1 C23.1 C24.1 C25.1 C26.1 C27.1 C28.2 C29.2 C30.2 C31.2 C32.2 C33.1 C34.1 C35.1 C36.1 C37.1 CN1.5 CN2.4 CN5.19 CN6.1 CN6.2 CN7.3 JP3.3 K1.3 K1.4 K2.3 K2.4 LED_VDD*.2 PYLK.A1 PYLK.A12 PYLK.B1 PYLK.B12 Q1.2 R1.1 R3.2 R5.1 R8.2 R20.1 R21.1 R25.1 R28.2 R30.1 R33.2 R60.1 U1.2 U2.2 U3.2 U4.2 U5.2 U6.2 U7.2 U8.2 U9.1 U10.2 U11.2 U12.2 U13.2 U14.2 U15.8 U15.23 U15.47 U16.2 U17.4 U18.51 U19.4 U20.2 U21.2 Y1.2 Y1.4 Y2.2 Y2.4 | length 5967.2
  Top Layer w6: C29.2@533.81,2746.26 593.37,2686.7 U18.51@658.3,2686.7 ; v1(1495.02,1265.12) 1525.02,1265.12 1538.08,1252.05 U5.2@1538.08,1221.81 ; U11.2@1580.22,342.61 U11.2@1582.71,340.12
  Top Layer w10: U7.2@153.56,1216.81 U7.2@154.29,1216.08 ; U7.2@154.55,1215.82 154.55,1180.19 159.38,1175.37 ; R30.1@195.02,535.12 200.02,540.12 v1(200.02,570.12) ; C16.1@210.02,210.12 210.02,200.12 C16.1@215.02,195.12 ; v1(255.02,1164.72) 265.9,1175.6 265.9,1215.43 U8.2@267.28,1216.81 ; C2.1@265.02,375.12 C2.1@270.02,380.12 ; C3.1@335.02,336.12 C3.1@336.02,335.12 ; R8.2@365.02,535.12 v1@453.96,535.12 ; v1(372.92,1155.82) 378.61,1161.51 U14.2@378.61,1216.71 ; R20.1@401.53,736 R20.1@403.05,737.51 ; v1(453.12,534.27) v1@453.96,535.12 ; R3.2@480.02,535.12 v1@453.96,535.12 ; U12.2@490.14,1216.81 491.43,1215.52 491.43,1172.73 501.84,1162.32 501.84,1156.94 v1@500.02,1155.12 ; C21.1@593.37,1020.12 603.37,1030.12 604.02,1030.12 597.97,1036.17 597.97,1054.26 619.25,1075.54 721.99,1075.54 756.84,1040.69 ; C17.1@628.61,509.61 C17.1@629.61,510.61 ; PYLK.A1@743.33,310.01 PYLK.B12@755.14,310.01 ; PYLK.B1@995.3,310.01 PYLK.A12@1007.11,310.01 ; v1@1039.49,613.67 v1@1039.62,613.8 ; v1@1041.63,614.13 1059.37,614.13 1088.59,584.91 1137.08,584.91 1154.93,567.07 C20.1@1154.93,537.75 ; U2.2@1314.28,1220.86 1317.11,1223.7 1317.11,1243.07 1334.16,1260.12 v1@1370.03,1260.12 ; v1(1369.22,1257.72) 1370.03,1258.53 v1@1370.03,1260.12 ; U1.2@1426.65,1221.81 1424.76,1223.7 1424.76,1245.37 1410.02,1260.12 v1@1370.03,1260.12 ; U10.2@1649.51,1221.81 1651.4,1219.92 1651.4,1194.07 1663.63,1181.84 1715.02,1181.84
  Top Layer w11: 756.84,1040.69 776.44,1021.1 U15.23@776.44,947.44 ; U15.47@953.6,612.8 953.6,656.03 959.75,662.19 982.1,662.19 1027.89,616.39 v1(1039.37,616.39) ; U15.8@1032.34,809.65 1199.95,809.65 1221.48,788.12 C22.1@1225.14,788.12
  Top Layer w12: Q1.2@50.22,1009.92 Q1.2@55.02,1005.11 ; v1(1561.72,954.38) 1566.86,954.38 1555.02,966.22 1555.02,1089 1579.41,1113.39 v1(1579.41,1113.63) ; C18.1@1711.02,1150.12 1715.02,1154.12 1715.02,1181.84 v1(1715.02,1200.12)
  Top Layer w15: U16.2@149.49,304.59 150.93,303.16 150.93,269.21 C16.1@210.02,210.12 ; C16.1@215.02,195.12 v1(272.58,195.12) ; U6.2@470.67,310.17 472.26,308.58 473.31,309.63 v1(498.1,309.63) ; v1(1210.02,150.12) U13.2@1260.02,150.12 1262.18,152.28 1294.67,152.28 1308.25,165.86 v1@1354.28,165.86 ; R25.1@1260.02,295.12 1279.29,295.12 v1(1295.06,310.88) ; v1(1355.02,165.12) 1355.02,209.56 1366.27,220.82 K1.4@1376.56,220.82 ; 1639.85,241.79 1640.37,241.27 1640.37,232.07 1651.63,220.82 K1.3@1674.56,220.82
  Top Layer w20: C16.1@210.02,210.12 v1(210.02,245.12) ; C2.1@270.02,380.12 v1(310.02,380.12) ; v1(309.85,832.4) 310.6,833.16 341.19,833.16 R21.1@341.94,833.92 ; C3.1@336.02,335.12 v1(365.02,335.12) ; R20.1@403.05,737.51 403.05,737.24 407.53,732.75 429.95,732.75 v1(430.72,731.99) ; v4(712.09,365.12) 715.04,365.12 PYLK.A1@749.19,330.97 ; CN1.5@915.02,1380.12 CN1.5@922.49,1387.59 ; CN7.3@920.02,1645.12 CN7.3@924.38,1640.76 ; PYLK.B1@999.52,326.39 999.52,327.74 1021.08,349.31 v4(1022.75,349.31) ; C22.1@1220.14,797.12 1225.14,792.12 1225.14,788.12 1225.42,788.4 1258.42,788.4 1270.14,800.12 v1(1270.14,867.69) 1293.97,891.52 1370.42,891.52 v1(1376.28,885.66) 1377.36,885.66 1380.46,888.76 1436.49,888.76 v1(1447.04,878.21) 1457.59,867.66 v1(1457.59,803.97) 1457.59,740.24 1457.59,592.57 v1(1435.14,570.12) 1419.87,554.85 1349.91,554.85 v1@1339.65,565.1 ; v1(1273.99,682.4) 1301.07,682.4 Y1.2@1316.67,666.81 1318.4,665.07 1318.4,591.85 1320.14,590.12 1324.14,590.12 1329.14,585.12 1329.14,575.62 C19.1@1330.39,574.37 ; 1330.39,570.75 v1(1337.84,563.29) ; C25.1@1382.14,840.12 1382.87,839.38 1382.87,754.16 Y1.4@1383.6,753.43 1396.76,740.27 v1(1457.56,740.27)
  Top Layer w25: 447.5,3210.12 499.4,3210.12 v2(499.4,3251.62) ; v2(475.32,3100.92) v2(460.47,3115.77) 445.62,3130.62 v2(445.62,3146.87) v2(445.62,3189.23) 445.62,3210.12 v2(445.62,3234.77) v2(467.07,3256.22) 499.4,3256.22 v2@522.55,3256.22 ; Y2.4@577.05,3212.5 v2(527.94,3261.61) v2@533.34,3267 ; C33.1@577.05,3273.44 Y2.4@577.05,3208.01 577.05,3313.71 ; C33.1@587.83,3273.44 539.78,3273.44 v2@533.34,3267 ; v2(620.37,3320.64) 577.05,3320.64 ; Y2.2@663.67,3141.08 v2(700.11,3141.08) v2(723.4,3164.37) v2(723.4,3204.83) v2(723.4,3245.29) 715.83,3252.86 v2(699.88,3268.81) v2(699.88,3302.4) v2(681.64,3320.64) 577.05,3320.64 ; v2(776.71,3138.2) 775.52,3139.39 v2(775.52,3268.31) 803.45,3296.25 826.04,3296.25 928.2,3296.25 929.21,3295.24 v2(963.42,3295.24) v2(989.11,3269.55) 989.11,3135.24 v2(984.3,3130.43) ; v2@533.34,3267 v2(533.34,3294.87) v2(559.11,3320.64) 577.05,3320.64
  Bottom Layer w6: v1@499.27,1157.95 v1(502.9,1157.95)
  Bottom Layer w10: v1(502.9,1157.95) 502.9,1239.6 572.48,1309.18 615.73,1309.18 638.02,1286.9 638.02,1215.9 665.91,1188.01 v1(665.91,1186.01) ; v1@665.02,1183.12 683.74,1164.39 750.83,1164.39 U3.2@751.55,1165.12
  Bottom Layer w20: CN1.5@915.02,1380.12 CN1.5@921.15,1386.25 ; CN7.3@918.95,1645.12 CN7.3@921.02,1643.05
  other v1: 765.02,70.12 867.52,70.12 970.02,70.12 1100.02,70.12 1462.26,73.12 1520.02,73.12 1730.02,80.12 1095.02,95.12 1730.02,140.12 1510.02,150.12 1560.02,150.12 775.02,165.12 865.02,165.12 970.02,165.12 1680.02,195.12 1560.02,285.12 1466.06,287.88 150.02,355.12 1635.02,575.12 1635.02,640.12 165.02,650.12 210.02,650.12 1460.14,660.12 57.32,975.46 60.02,1035.12 1182.37,1167.68 1241.96,1265.06 35.02,1375.12 659.02,1404.12 767.02,1427.12 970.02,1427.12 875.02,1428.12 614.02,1433.12 1285.02,1480.12 1380.02,1480.12 1495.02,1480.12 1730.02,1480.12 35.02,1485.12 1075.02,1489.12 143.02,1490.12 678.02,1497.12 606.02,1498.12 770.02,1498.12 973.02,1498.12 873.02,1499.12 921.02,1506.12 588.58,3831.1 460.02,3834.42
  other v2: 500.25,72.84 574.49,72.84 601.48,476.84 600.22,528.32 1223.07,527.88 239.95,578.3 704.44,621.71 833.65,684.06 768.48,684.62 445.72,923.79 1531.35,954.64 1597.77,958.5 464.87,967.74 1064.86,976.23 1104.63,990.4 863.56,1001.69 1313.61,1033.18 1368.6,1033.57 1256.67,1033.96 1421.25,1034.75 1530.69,1035.67 284.02,1062.12 195.02,1139.12 1235.3,1180.59 1227.21,1219.01 1711.7,1229.89 1713.33,1260.76 1186.61,1411.66 88.62,1424.12 29.32,1434.22 1113.97,2838.9 989.11,3202.4 775.52,3203.85 861.46,3295.63 899.42,3296.76 1401.02,3503.12 1383.02,3552.12 1525.8,3697.92
  other v3: 1221.69,1491.55 1224.41,1629.13 1638.06,1644.88 1738.06,1669.88 251.06,1744.88 529.06,1748.88 444.06,1834.88 338.06,1844.88 688.06,1869.88 513.06,2219.88 613.06,2244.88 588.06,2319.88 1254.72,2327.17 1377.17,2329.53 1114.96,2333.46 763.06,2444.88 788.06,2569.88 1213.06,2844.88 442.06,2941.88 443.06,3013.88 1263.06,3069.88 1388.06,3169.88 1263.06,3244.88 1388.06,3344.88 163.06,3519.88 63.06,3569.88 413.06,3569.88 588.06,3569.88 813.06,3669.88 1020.62,3670.52 63.06,3694.88 463.06,3694.88 1463.06,3694.88 1663.06,3694.88 255.8,3697.92 849.61,3789.37 738.06,3794.88 938.06,3819.88 1113.06,3819.88
L_USB_CN_DM: PYLK.A7 PYLK.B7 U6.4 | length 509.8
  Top Layer w6: U6.4@568.17,272.71 569.19,271.69 569.19,254.57 596.05,227.71 816.38,227.71 845.51,256.84 PYLK.B7@845.51,309.83 ; PYLK.B7@845.69,310.01 844.91,310.78 844.91,355.01 855.02,365.12 875.02,365.12 885.25,354.88 PYLK.A7@885.25,310.2
L_USB_CN_DP: PYLK.A6 PYLK.B6 U6.6 | length 673.6
  Top Layer w6: U6.6@568.17,347.52 567.28,346.63 540.41,346.63 530.37,336.58 530.37,240.51 563.23,207.65 829.82,207.65 866.33,244.15 870.06,240.42 899.08,240.42 904.33,245.67 PYLK.B6@904.33,309.59 ; 865.76,244.72 PYLK.A6@865.76,309.62
LED_BLUE: R9.2 U15.28 | length 675.2
  Top Layer w6: R9.2@220.02,710.12 225.05,710.12 303.28,631.89 438.54,631.89 521.35,714.7 521.35,827.53 543.93,850.12 575.02,850.12 595.81,829.33 U15.28@697.7,829.33
LED_GREEN: R6.2 U15.26 | length 724.3
  Top Layer w6: R6.2@220.02,820.12 291.84,748.3 291.84,725.78 335.38,682.25 432.28,682.25 483.49,733.46 483.49,848.59 541.76,906.86 591.92,906.86 630.09,868.7 U15.26@697.7,868.7
LED_RED: R4.2 U15.27 | length 692.2
  Top Layer w6: R4.2@220.02,765.12 224.08,765.12 335.04,654.16 432.15,654.16 502.7,724.71 502.7,837.8 540.02,875.12 590.02,875.12 616.12,849.02 U15.27@697.7,849.02
NetC1_2: C1.2 PYLK.1 PYLK.2 PYLK.3 PYLK.4 R8.1 | length 1430.2
  Top Layer w8: R8.1@365.02,475.12 368.31,471.82 368.31,443.98 424.65,387.64 611.99,387.64 705.14,294.49 PYLK.1@705.14,284.41 ; PYLK.3@705.14,119.84 PYLK.4@1045.29,119.84 PYLK.2@1045.29,284.41
  Bottom Layer w8: PYLK.3@705.14,119.84 839.31,119.84 C1.2@839.87,119.29 ; PYLK.1@716.05,295.33 PYLK.2@1034.38,295.33
  Bottom Layer w20: PYLK.1@705.14,284.41 PYLK.1@716.05,295.33 ; PYLK.2@1034.38,295.33 PYLK.2@1045.29,284.41
NetC17_2: C17.2 R31.2 | length 64.1
  Top Layer w6: 686.23,571.86 686.23,514 C17.2@690.61,509.61
NetC27_2: C27.2 K2.1 K2.2 R50.1 R70.2 U20.1 | length 562.5
  Top Layer w6: K2.1@108.8,3783.62 K2.2@406.8,3783.62 480.16,3783.62 491.89,3771.89 U20.1@513.51,3771.89 557.43,3771.89 C27.2@557.48,3771.94 665.57,3771.94 R70.2@666.14,3772.52
NetC33_2: C33.2 R55.1 Y2.3 | length 238.9
  Top Layer w6: 627.28,3065.31 620.7,3071.89 620.7,3172.79 655.92,3208.01 Y2.3@663.67,3208.01 663.67,3259.6 C33.2@649.83,3273.44
NetC34_2: C34.2 R57.1 Y2.1 | length 158.7
  Top Layer w6: C34.2@499.4,3148.12 570.02,3148.12 Y2.1@577.05,3141.08 576.19,3140.21 576.19,3063.31
NetC35_2: C35.2 K3.3 K3.4 R58.1 R60.2 U21.1 | length 699.1
  Top Layer w6: R60.2@1176.21,3736.35 1233.18,3736.35 C35.2@1234.75,3734.78 1242.19,3742.22 U21.1@1284.25,3742.22 v3(1322.74,3742.22) 1322.83,3742.13 1363.78,3742.13 1377.95,3756.3 K3.4@1377.95,3783.9 K3.3@1675.95,3783.9
  Bottom Layer w6: R58.1@1287.01,3594.87 1287.01,3706.5 v3(1322.74,3742.22)
NetC36_2: C36.2 R59.1 Y3.2 | length 176.8
  Top Layer w6: 901.68,3085.94 901.68,3119.48 927.31,3145.12 927.31,3177.47 927.31,3231.34 C36.2@929.21,3233.24 ; Y3.2@927.31,3156.51 Y3.2@927.31,3174.62
NetC37_2: C37.2 R61.1 Y3.1 | length 159.6
  Top Layer w6: C37.2@826.04,3234.25 826.92,3233.37 Y3.1@826.92,3156.51 826.92,3143.24 852,3118.16 852,3085.43
NetJP3_2: JP3.2 R56.1 | length 222.4
  Bottom Layer w8: JP3.2@410.06,1631.88 410.06,1678.88 R56.1@534.06,1802.88
NetLED1_2: LED1.2 R9.1 | length 846.1
  Top Layer w6: R9.1@160.02,710.12 157.68,712.45 100.35,712.45 48.02,660.12 48.02,171.12 63.82,155.32 85.88,155.32 107.55,133.65 107.55,84.28 143.84,47.99 175.09,47.99 LED1.2@186.04,58.93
